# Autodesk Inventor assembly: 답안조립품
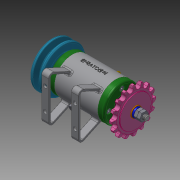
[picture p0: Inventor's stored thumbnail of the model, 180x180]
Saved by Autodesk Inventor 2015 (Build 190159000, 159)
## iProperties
Created: 2021-12
Part Number: 답안조립품
Document SubType Name: Assembly
Designer: pc-04
Author: pc-04
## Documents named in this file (16)
- C:\Users\pc-04\Desktop\711206V1018\답안조립품.iam
- C:\Users\pc-04\Desktop\711206V1018\본체.ipt
- C:\Users\pc-04\Desktop\711206V1018\커버.ipt
- C:\Users\pc-04\Desktop\711206V1018\베어링 6002.ipt
- C:\Users\pc-04\Desktop\711206V1018\축.ipt
- C:\Users\pc-04\Desktop\711206V1018\오일 실 15 x 25 x 7.ipt
- C:\Users\pc-04\Desktop\711206V1018\키 3 x 3.ipt
- C:\Users\pc-04\Desktop\711206V1018\V벨트풀리.ipt
- C:\Users\pc-04\Desktop\711206V1018\스프로킷.ipt
- C:\Users\pc-04\Desktop\711206V1018\와셔 8 x 17.ipt
- C:\Users\pc-04\Desktop\711206V1018\스프링와셔 8.ipt
- C:\Users\pc-04\Desktop\711206V1018\너트 M8.ipt
- C:\Users\pc-04\Desktop\711206V1018\와셔 6 x 11.5.ipt
- C:\Users\pc-04\Desktop\711206V1018\볼트 M6 x 8.ipt
- C:\Users\pc-04\Desktop\711206V1018\니플 M6 x 0.75.ipt
- C:\Users\pc-04\Desktop\711206V1018\볼트 M4 x 12.ipt
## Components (11 placed, 3 different names)
1. KS B 2023 6002 - 15 x 32 x 9:1
2. KS B 2023 6002 - 15 x 32 x 9:2
3. V벨트풀리:1
4. ISO 4762 M4 x 12:1
5. ISO 4762 M4 x 12:2
6. ISO 4762 M4 x 12:3
7. ISO 4762 M4 x 12:4
8. ISO 4762 M4 x 12:5
9. ISO 4762 M4 x 12:6
10. ISO 4762 M4 x 12:7
11. ISO 4762 M4 x 12:8
